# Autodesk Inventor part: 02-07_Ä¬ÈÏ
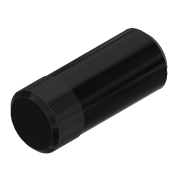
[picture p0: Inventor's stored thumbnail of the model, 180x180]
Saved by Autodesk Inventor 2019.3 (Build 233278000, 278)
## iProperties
Created: 2010-06
Part Number: 02-07_Ä¬ÈÏ
Material: Ogólny
Document SubType Name: Modeling
Designer: CADENGINEERING4
Density: 1 g/cm^3
Appearance: Gładki — czarny
Author: CADENGINEERING4
Revision Number: ÈÎºÎ
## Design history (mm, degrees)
feature "NONE"
node "Bryła1"
